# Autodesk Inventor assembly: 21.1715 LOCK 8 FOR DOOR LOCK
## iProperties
Created: 2007-11
Part Number: 21.1715 LOCK 8 FOR DOOR LOCK
Document SubType Name: Assembly
Designer: Andy Moles
Author: Andy Moles
